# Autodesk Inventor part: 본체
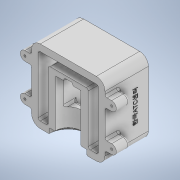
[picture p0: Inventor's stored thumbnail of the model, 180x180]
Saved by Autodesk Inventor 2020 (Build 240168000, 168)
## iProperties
Created: 2022-03
Part Number: 본체
Material: 일반
Document SubType Name: Modeling
Designer: Administrator
Density: 1 g/cm^3
Appearance: 기본값
Author: Administrator
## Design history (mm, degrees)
sketch "스케치1"
  geometry: L1 (-55, -55)-(55, -55); L2 (55, -55)-(55, 55); L3 (55, 55)-(-55, 55); L4 (-55, 55)-(-55, -55); L5 (-55, -55)-(55, 55); L6 (55, -55)-(-55, 55); 1 further point
  constraints: 12 end point, 2 midpoint, 2 parallel, 1 horizontal, 1 perpendicular
  dimensions: "d0" = 110 distance of L2.end L3.end; "d1" = 110 distance of L1.end L2.end
extrude "돌출1" new body sketch "스케치1" stored distance "d2" = 65; taper "d3" = 0 deg
sketch "스케치2"
  geometry: L1 (0, 0)-(110, 0) reference; C1 r 28 at (55, 0); 1 further point
  constraints: 1 centre point, 1 midpoint
  dimensions: "d4" = 56 diameter of C1
extrude "돌출2" cut sketch "스케치2" distance "d5" = 8; taper "d6" = 0 deg
sketch "스케치3"
  geometry: C1 r 19 at (55, 0); A1 r 28 centre (55, 0) between (27, 0) and (83, 0) reference; 1 further point
  constraints: 1 centre point, 1 coincident
  dimensions: "d7" = 38 diameter of C1
extrude "돌출3" cut sketch "스케치3" distance "d8" = 72; taper "d9" = 0 deg
sketch "스케치4"
  geometry: L1 (36, 0)-(74, 0) reference; C1 r 7.5 at (55, 0); A1 r 19 centre (55, 0) between (36, 0) and (74, 0) reference; 1 further point
  constraints: 1 centre point, 1 coincident
  dimensions: "d10" = 15 diameter of C1
extrude "돌출4" cut sketch "스케치4" distance "d11" = 4; taper "d12" = -30 deg
sketch "스케치5"
  geometry: A1 r 5.191 centre (55, 0) between (49.809, 0) and (60.191, 0) reference; 2 further points
  constraints: 1 vertical alignment
  dimensions: "d13" = 23 distance of point (55, -23) A1.centre
hole "구멍1" sketch "스케치5" at (55, -23) diameter "d14" = 3.242; stored, may be unused: countersink angle "d18" = 90 deg, drill point angle "d20" = 118 deg; dims "d15" = 9, "d16" = 4, "d17" = 2, "d19" = 11
fillet "모깎기1" dims "d21" = 1
chamfer "모따기1" distance "d22" = 1; stored, may be unused: second distance "d23" = 2, angle "d24" = 45 deg
sketch "스케치7"
  geometry: L1 (-45, 45)-(-45, -45); L2 (-45, -45)-(-30, -45); L3 (-30, -45)-(-30, 33); L4 (-30, 33)-(30, 33); L5 (30, 33)-(30, -45); L6 (30, -45)-(45, -45); L7 (45, -45)-(45, 45); L8 (45, 45)-(-45, 45); L9 (29, -55)-(55, -55) reference; L10 (55, -55)-(55, 55) reference; L11 (-55, 55)-(-55, -55) reference; L12 (55, 55)-(-55, 55) reference; 1 further point
  constraints: 16 end point, 5 perpendicular, 2 point on line, 2 vertical
  dimensions: "d25" = 10 distance between parallel lines of L9 L6; "d26" = 10 distance between parallel lines of L10 L7; "d27" = 10 distance between parallel lines of L11 L1; "d28" = 10 distance between parallel lines of L12 L8; "d29" = 25 distance between parallel lines of L10 L5; "d30" = 22 distance between parallel lines of L12 L4; "d31" = 25 distance between parallel lines of L11 L3
extrude "돌출5" cut sketch "스케치7" extent not by distance; stored distance "d32" = 0; taper "d33" = 0 deg
sketch "스케치10"
  geometry: L1 (19, 23)-(-19, 23); L2 (-19, 23)-(-19, 6.343); L3 (-19, 6.343)-(-55, -3.303); L4 (19, 23)-(19, -1.075); L5 (19, -1.075)-(-55, -20.903); L6 (-55, 32.5)-(-55, 3.5) reference; L7 (-55, 32.5)-(-55, 32.5) reference; L8 (-55, 32.5)-(-55, -32.5) reference; L9 (-55, -32.5)-(-55, 32.5) reference; L10 (-46, 13.5)-(24, 13.5) reference; L11 (24, 32.5)-(24, 13.5) reference; L12 (33, -2.5)-(-40.778, -22.269); L13 (33, 32.5)-(33, -32.5) reference; L14 (33, -32.5)-(-45, -32.5) reference; 7 further points
  constraints: 12 end point, 3 point on line, 2 midpoint, 2 parallel, 1 horizontal, 1 horizontal alignment, 1 perpendicular, 1 vertical
  dimensions: "d37" = 17 distance between parallel lines of L5 L3; "d38" = 38 distance between parallel lines of L2 L4; "d39" = 36 distance between parallel lines of L6 L2; "d40" = 30 distance from line of L14 L12.start; "d41" = 75 deg angle of L12 L13; "d42" = 5 distance between parallel lines of L5 L12
extrude "돌출6" cut sketch "스케치10" stored distance "d43" = 34; taper "d44" = 0 deg
fillet "모깎기2" dims "d45" = 3
fillet "모깎기3" dims "d46" = 3
fillet "모깎기5" dims "d48" = 3
fillet "모깎기6" dims "d49" = 3
sketch "스케치11"
  geometry: L1 (33, -2.5)-(-38.903, -21.766); L2 (33, 32.5)-(33, -32.5) reference; L3 (33, -32.5)-(-45, -32.5) reference; L4 (-38.903, -21.766)-(-45, -23.4); L5 (-45, -23.4)-(-45, -32.5); L6 (-55, -32.5)-(-55, 32.5) reference; 1 further point
  constraints: 6 end point, 3 point on line, 1 perpendicular
  dimensions: "d50" = 30 distance from line of L3 L1.start; "d51" = 75 deg angle of L1 L2; "d71" = 10 distance between parallel lines of L6 L5
extrude "돌출7" cut sketch "스케치11" stored distance "d52" = 60; taper "d53" = 0 deg
fillet "모깎기7" dims "d54" = 3
fillet "모깎기8" dims "d55" = 3
fillet "모깎기9" dims "d56" = 13
sketch "스케치12"
  geometry: L1 (42, 55)-(-42, 55) reference; L2 (0, 0)-(0, 9.926); L3 (-65, 35)-(-55, 35); L4 (-55, 42)-(-55, -42) reference; L5 (-65, -21)-(-55, -21); L6 (-65, 21)-(-55, 21); L7 (-65, -35)-(-55, -35); L8 (65, 21)-(55, 21); L9 (65, 35)-(55, 35); L10 (65, -21)-(55, -21); L11 (65, -35)-(55, -35); L12 (55, 35)-(55, 21); L13 (55, 42)-(55, -42) reference; L14 (55, -21)-(55, -35); A1 r 7 centre (-65, -28) between (-65, -21) and (-65, -35); A2 r 7 centre (-65, 28) between (-65, 35) and (-65, 21); A3 r 7 centre (65, 28) between (65, 21) and (65, 35); A4 r 7 centre (65, -28) between (65, -35) and (65, -21)
  constraints: 22 end point, 10 symmetric about line, 8 point on circle, 4 centre point, 4 point on line, 4 tangent, 3 perpendicular, 2 collinear, 1 equal radius, 1 horizontal, 1 vertical, 1 vertical alignment, 2 other
  dimensions: "d57" = 14 diameter of A2; "d58" = 56 distance of A1.centre A2.centre; "d59" = 27 distance from line of L1 A2.centre; "d60" = 65 horizontal distance of L2.start A2.centre
extrude "돌출8" join sketch "스케치12" distance "d61" = 20; taper "d62" = 0 deg
sketch "스케치13"
  geometry: A1 r 7 centre (-65, 28) between (-65, 35) and (-65, 21) reference; A2 r 7 centre (-65, -28) between (-65, -21) and (-65, -35) reference; A3 r 7 centre (65, 28) between (65, 21) and (65, 35) reference; A4 r 7 centre (65, -28) between (65, -35) and (65, -21) reference; 5 further points
  constraints: 4 coincident
hole "구멍2" sketch "스케치13" at (-65, 28), (-65, -28), (65, 28), (65, -28) diameter "d63" = 3.242; stored, may be unused: countersink angle "d67" = 90 deg, drill point angle "d69" = 118 deg; dims "d64" = 9, "d65" = 4, "d66" = 2, "d68" = 11
fillet "모깎기10" dims "d72" = 3
sketch "스케치14"
  geometry: L1 (0, 84)-(0, 0) reference; L2 (-65, -13)-(0, -13) reference; 2 further points
  constraints: 1 other
  dimensions: "d73" = 20 distance from line of L1 point (-20, 42); "d74" = 55 distance from line of L2 point (-20, 42)
feature "엠보싱1" sketch "스케치14" dims "d0" = 110, "d1" = 110, "d75" = 0.5, "d76" = 0
fillet "모깎기11" dims "d77" = 3
fillet "모깎기12" dims "d78" = 1
fillet "모깎기13" dims "d79" = 3
fillet "모깎기14" dims "d80" = 3
fillet "모깎기15" dims "d81" = 3
fillet "모깎기16" dims "d82" = 3
node "솔리드1"
node "투영된 루프1"
node "투영된 루프2"
feature "A9D066F2-1C7D-4E18-AEED-F7BC21143FA4" dims "d14" = 3.242, "d15" = 9, "d16" = 4, "d17" = 2, "d18" = 90 deg, "d19" = 11, "d20" = 118 deg
